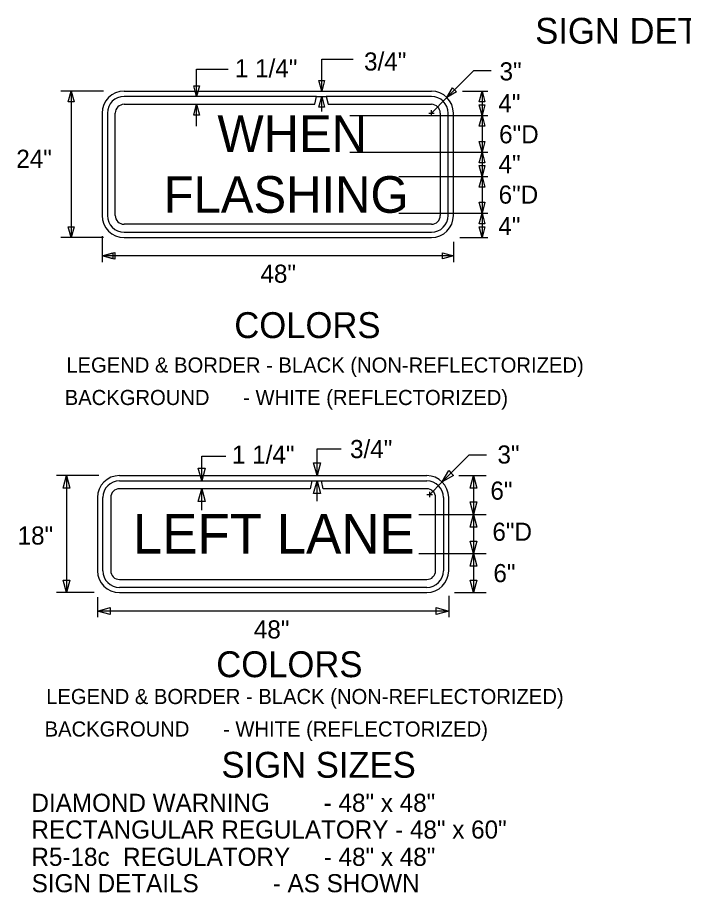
# Model space of a CAD drawing. Extents: x 15278 to 18126, y 1908 to 6555.
# Drawn here: x 17436.4 to 17744.9, y 2193.3 to 2599 of the extents above; entities that cross this region are included whole.
import ezdxf

# ---------------------------------------------------------------- set-up
doc = ezdxf.new("R2010")
doc.units = 0
for name, color, linetype in [('MT_SCRATCH_LEVEL_A', 7, 'Continuous'), ('TYPICAL_EX', 7, 'Continuous'), ('TYPICAL_TEXT_DIMEN_EX', 7, 'Continuous'), ('TYPICAL_TEXT_DIMEN_PR', 7, 'Continuous')]:
    doc.layers.add(name, color=color, linetype=linetype)

msp = doc.modelspace()

# ---------------------------------------------------------------- linework, layer by layer
at = {"layer": 'MT_SCRATCH_LEVEL_A'}
for p, q in [((17577.3, 2579.66), (17591.85, 2579.66)), ((17519.35, 2575.12), (17533.9, 2575.12)), ((17635.31, 2561.91), (17647.66, 2574.32)), ((17655.86, 2574.32), (17647.66, 2574.32)), ((17628.16, 2554.73), (17635.31, 2561.91)), ((17628.16, 2553.51), (17628.16, 2556.01)), ((17626.91, 2554.73), (17629.41, 2554.73)), ((17475.57, 2497.7), (17475.57, 2485.62)), ((17638.33, 2494.97), (17638.33, 2485.62)), ((17638.33, 2488.53), (17475.57, 2488.53)), ((17575.14, 2399.05), (17586.28, 2399.05)), ((17521.69, 2395.58), (17532.82, 2395.58)), ((17633.15, 2383.67), (17645.48, 2396.05)), ((17653.65, 2396.05), (17645.48, 2396.05)), ((17627.35, 2377.85), (17633.15, 2383.67)), ((17626.06, 2377.85), (17628.6, 2377.85)), ((17627.35, 2376.63), (17627.35, 2379.11)), ((17473.44, 2330.34), (17473.44, 2320.93)), ((17636.16, 2330.92), (17636.16, 2320.93)), ((17636.16, 2323.85), (17473.44, 2323.85))]:
    msp.add_line(p, q, dxfattribs=at)
at = {"layer": 'TYPICAL_EX'}
for p, q in [((17485.74, 2564.87), (17628.16, 2564.87)), ((17574.89, 2562.43), (17485.74, 2562.43)), ((17574.07, 2558.77), (17574.89, 2562.43)), ((17574.89, 2562.43), (17579.3, 2562.43)), ((17628.16, 2562.43), (17579.3, 2562.43)), ((17579.3, 2562.43), (17580.24, 2558.77)), ((17485.74, 2558.77), (17574.07, 2558.77)), ((17580.24, 2558.77), (17628.16, 2558.77)), ((17475.57, 2554.7), (17475.57, 2507.22)), ((17478.01, 2554.7), (17478.01, 2507.22)), ((17481.67, 2507.22), (17481.67, 2554.7)), ((17632.23, 2554.7), (17632.23, 2507.22)), ((17635.89, 2507.22), (17635.89, 2554.7)), ((17638.33, 2507.22), (17638.33, 2554.7)), ((17628.16, 2503.15), (17485.74, 2503.15)), ((17485.74, 2499.49), (17628.16, 2499.49)), ((17485.74, 2497.04), (17628.16, 2497.04)), ((17483.61, 2386.63), (17625.99, 2386.63)), ((17483.61, 2384.19), (17572.73, 2384.19)), ((17572.73, 2384.19), (17571.92, 2380.53)), ((17572.73, 2384.19), (17577.14, 2384.19)), ((17571.92, 2380.53), (17483.61, 2380.53)), ((17473.44, 2376.46), (17473.44, 2342.53)), ((17475.88, 2342.53), (17475.88, 2376.46)), ((17479.54, 2376.46), (17479.54, 2342.53)), ((17636.16, 2342.53), (17636.16, 2376.46)), ((17483.61, 2338.46), (17625.99, 2338.46)), ((17625.99, 2334.8), (17483.61, 2334.8)), ((17483.61, 2332.36), (17625.99, 2332.36))]:
    msp.add_line(p, q, dxfattribs=at)
for centre, radius, start, end in [((17485.74, 2554.7), 10.17, 90, 180), ((17628.16, 2554.7), 10.17, 0, 90), ((17485.74, 2554.7), 7.73, 90, 180), ((17628.16, 2554.7), 7.73, 0, 90), ((17485.74, 2554.7), 4.07, 90, 180), ((17628.16, 2554.7), 4.07, 0, 90), ((17485.74, 2507.21), 10.17, 180, 270), ((17485.74, 2507.21), 7.73, 180, 270), ((17485.74, 2507.21), 4.07, 180, 270), ((17628.16, 2507.21), 10.17, 270, 0), ((17628.16, 2507.21), 4.07, 270, 0), ((17628.16, 2507.21), 7.73, 270, 0), ((17483.61, 2376.46), 10.17, 90, 180), ((17625.99, 2376.46), 10.17, 0, 90), ((17483.61, 2376.46), 7.73, 90, 180), ((17483.61, 2376.46), 4.07, 90, 180), ((17483.61, 2342.53), 10.17, 180, 270), ((17483.61, 2342.53), 7.73, 180, 270), ((17483.61, 2342.53), 4.07, 180, 270), ((17625.99, 2342.53), 10.17, 270, 0), ((17625.99, 2342.53), 7.73, 270, 0), ((17625.99, 2342.53), 4.07, 270, 0)]:
    msp.add_arc(centre, radius, start, end, dxfattribs=at)
at = {"layer": 'TYPICAL_TEXT_DIMEN_PR'}
for p, q in [((17577.3, 2564.87), (17577.3, 2579.66)), ((17519.35, 2562.43), (17519.35, 2575.12)), ((17577.3, 2564.87), (17575.96, 2569.85)), ((17575.96, 2569.85), (17577.3, 2569.85)), ((17577.3, 2569.85), (17578.63, 2569.85)), ((17578.63, 2569.85), (17577.3, 2564.87)), ((17476.23, 2564.87), (17456.48, 2564.87)), ((17459.87, 2559.89), (17461.2, 2564.87)), ((17461.2, 2564.87), (17461.2, 2497.04)), ((17461.2, 2564.87), (17462.54, 2559.89)), ((17519.35, 2562.43), (17518.02, 2567.41)), ((17518.02, 2567.41), (17519.35, 2567.41)), ((17519.35, 2567.41), (17520.69, 2567.41)), ((17520.69, 2567.41), (17519.35, 2562.43)), ((17635.31, 2561.91), (17637.88, 2566.39)), ((17639.77, 2564.5), (17635.31, 2561.91)), ((17637.88, 2566.39), (17638.82, 2565.45)), ((17638.82, 2565.45), (17639.77, 2564.5)), ((17642.6, 2564.87), (17654.29, 2564.87)), ((17650.26, 2559.89), (17651.59, 2564.87)), ((17651.59, 2564.87), (17651.59, 2553.55)), ((17651.59, 2564.87), (17652.92, 2559.89)), ((17461.2, 2559.89), (17459.87, 2559.89)), ((17462.54, 2559.89), (17461.2, 2559.89)), ((17575.96, 2557.45), (17577.3, 2562.43)), ((17577.3, 2555.4), (17577.3, 2562.43)), ((17577.3, 2562.43), (17578.63, 2557.45)), ((17651.59, 2559.89), (17650.26, 2559.89)), ((17652.92, 2559.89), (17651.59, 2559.89)), ((17518.02, 2553.78), (17519.35, 2558.77)), ((17519.35, 2548.68), (17519.35, 2558.77)), ((17519.35, 2558.77), (17520.69, 2553.78)), ((17577.3, 2557.45), (17575.96, 2557.45)), ((17578.63, 2557.45), (17577.3, 2557.45)), ((17651.59, 2553.55), (17650.26, 2558.53)), ((17650.26, 2558.53), (17651.59, 2558.53)), ((17651.59, 2558.53), (17652.92, 2558.53)), ((17652.92, 2558.53), (17651.59, 2553.55)), ((17519.35, 2553.78), (17518.02, 2553.78)), ((17520.69, 2553.78), (17519.35, 2553.78)), ((17590.39, 2553.55), (17654.29, 2553.55)), ((17650.26, 2548.57), (17651.59, 2553.55)), ((17651.59, 2553.55), (17651.59, 2536.57)), ((17651.59, 2553.55), (17652.92, 2548.57)), ((17651.59, 2548.57), (17650.26, 2548.57)), ((17652.92, 2548.57), (17651.59, 2548.57)), ((17651.59, 2536.57), (17650.26, 2541.55)), ((17650.26, 2541.55), (17651.59, 2541.55)), ((17651.59, 2541.55), (17652.92, 2541.55)), ((17652.92, 2541.55), (17651.59, 2536.57)), ((17590.39, 2536.57), (17654.29, 2536.57)), ((17650.26, 2531.59), (17651.59, 2536.57)), ((17651.59, 2536.57), (17651.59, 2525.34)), ((17651.59, 2536.57), (17652.92, 2531.59)), ((17651.59, 2531.59), (17650.26, 2531.59)), ((17652.92, 2531.59), (17651.59, 2531.59)), ((17651.59, 2525.34), (17650.26, 2530.33)), ((17650.26, 2530.33), (17651.59, 2530.33)), ((17651.59, 2525.34), (17650.26, 2530.33)), ((17650.26, 2530.33), (17651.59, 2530.33)), ((17651.59, 2530.33), (17652.92, 2530.33)), ((17652.92, 2530.33), (17651.59, 2525.34)), ((17651.59, 2530.33), (17652.92, 2530.33)), ((17652.92, 2530.33), (17651.59, 2525.34)), ((17612.99, 2525.34), (17654.29, 2525.34)), ((17650.26, 2520.36), (17651.59, 2525.34)), ((17651.59, 2525.34), (17651.59, 2508.36)), ((17651.59, 2525.34), (17652.92, 2520.36)), ((17651.59, 2520.36), (17650.26, 2520.36)), ((17652.92, 2520.36), (17651.59, 2520.36)), ((17651.59, 2508.36), (17650.26, 2513.35)), ((17650.26, 2513.35), (17651.59, 2513.35)), ((17651.59, 2508.36), (17650.26, 2513.35)), ((17650.26, 2513.35), (17651.59, 2513.35)), ((17651.59, 2513.35), (17652.92, 2513.35)), ((17652.92, 2513.35), (17651.59, 2508.36)), ((17651.59, 2513.35), (17652.92, 2513.35)), ((17652.92, 2513.35), (17651.59, 2508.36)), ((17612.99, 2508.36), (17654.29, 2508.36)), ((17650.26, 2503.38), (17651.59, 2508.36)), ((17651.59, 2508.36), (17651.59, 2497.04)), ((17651.59, 2508.36), (17652.92, 2503.38)), ((17651.59, 2503.38), (17650.26, 2503.38)), ((17652.92, 2503.38), (17651.59, 2503.38)), ((17461.2, 2497.04), (17459.87, 2502.03)), ((17459.87, 2502.03), (17461.2, 2502.03)), ((17461.2, 2502.03), (17462.54, 2502.03)), ((17462.54, 2502.03), (17461.2, 2497.04)), ((17651.59, 2497.04), (17650.26, 2502.03)), ((17650.26, 2502.03), (17651.59, 2502.03)), ((17651.59, 2502.03), (17652.92, 2502.03)), ((17652.92, 2502.03), (17651.59, 2497.04)), ((17476.23, 2497.04), (17456.48, 2497.04)), ((17641.35, 2497.04), (17654.29, 2497.04)), ((17475.57, 2488.53), (17481.43, 2490.1)), ((17475.57, 2488.53), (17480.55, 2489.87)), ((17481.43, 2486.96), (17475.57, 2488.53)), ((17480.55, 2487.2), (17475.57, 2488.53)), ((17480.55, 2489.87), (17480.55, 2488.53)), ((17480.55, 2488.53), (17480.55, 2487.2)), ((17481.43, 2490.1), (17481.43, 2488.53)), ((17481.43, 2488.53), (17481.43, 2486.96)), ((17633.35, 2488.53), (17633.35, 2489.87)), ((17633.35, 2489.87), (17638.33, 2488.53)), ((17638.33, 2488.53), (17633.35, 2487.2)), ((17633.35, 2487.2), (17633.35, 2488.53)), ((17575.14, 2386.63), (17575.14, 2399.05)), ((17521.69, 2384.19), (17521.69, 2395.58)), ((17521.69, 2384.19), (17520.12, 2390.05)), ((17520.12, 2390.05), (17521.69, 2390.05)), ((17521.69, 2390.05), (17523.26, 2390.05)), ((17523.26, 2390.05), (17521.69, 2384.19)), ((17575.14, 2386.63), (17573.57, 2392.49)), ((17573.57, 2392.49), (17575.14, 2392.49)), ((17575.14, 2392.49), (17576.71, 2392.49)), ((17576.71, 2392.49), (17575.14, 2386.63)), ((17474.08, 2386.63), (17454.36, 2386.63)), ((17457.5, 2380.77), (17459.07, 2386.63)), ((17459.07, 2386.63), (17459.07, 2332.36)), ((17459.07, 2386.63), (17460.64, 2380.77)), ((17633.15, 2383.67), (17636.17, 2388.93)), ((17638.4, 2386.72), (17633.15, 2383.67)), ((17636.17, 2388.93), (17637.28, 2387.83)), ((17637.28, 2387.83), (17638.4, 2386.72)), ((17640.78, 2386.63), (17653.49, 2386.63)), ((17646.12, 2380.77), (17647.69, 2386.63)), ((17647.69, 2386.63), (17647.69, 2368.54)), ((17647.69, 2386.63), (17649.26, 2380.77)), ((17483.61, 2384.19), (17572.73, 2384.19)), ((17572.73, 2384.19), (17571.92, 2380.53)), ((17573.57, 2378.33), (17575.14, 2384.19)), ((17575.14, 2374.83), (17575.14, 2384.19)), ((17575.14, 2384.19), (17576.71, 2378.33)), ((17578.06, 2380.53), (17577.14, 2384.19)), ((17577.14, 2384.19), (17625.99, 2384.19)), ((17459.07, 2380.77), (17457.5, 2380.77)), ((17460.64, 2380.77), (17459.07, 2380.77)), ((17571.92, 2380.53), (17483.61, 2380.53)), ((17520.12, 2374.67), (17521.69, 2380.53)), ((17521.69, 2370.54), (17521.69, 2380.53)), ((17521.69, 2380.53), (17523.26, 2374.67)), ((17575.14, 2378.33), (17573.57, 2378.33)), ((17576.71, 2378.33), (17575.14, 2378.33)), ((17625.99, 2380.53), (17578.06, 2380.53)), ((17647.69, 2380.77), (17646.12, 2380.77)), ((17649.26, 2380.77), (17647.69, 2380.77)), ((17475.88, 2342.53), (17475.88, 2376.46)), ((17479.54, 2376.46), (17479.54, 2342.53)), ((17521.69, 2374.67), (17520.12, 2374.67)), ((17523.26, 2374.67), (17521.69, 2374.67)), ((17630.06, 2342.53), (17630.06, 2376.46)), ((17633.72, 2376.46), (17633.72, 2342.53)), ((17647.69, 2368.54), (17646.12, 2374.4)), ((17646.12, 2374.4), (17647.69, 2374.4)), ((17647.69, 2374.4), (17649.26, 2374.4)), ((17649.26, 2374.4), (17647.69, 2368.54)), ((17622.35, 2368.54), (17653.49, 2368.54)), ((17646.12, 2362.68), (17647.69, 2368.54)), ((17647.69, 2368.54), (17647.69, 2350.45)), ((17647.69, 2368.54), (17649.26, 2362.68)), ((17647.69, 2362.68), (17646.12, 2362.68)), ((17649.26, 2362.68), (17647.69, 2362.68)), ((17647.69, 2350.45), (17646.12, 2356.31)), ((17646.12, 2356.31), (17647.69, 2356.31)), ((17647.69, 2356.31), (17649.26, 2356.31)), ((17649.26, 2356.31), (17647.69, 2350.45)), ((17622.35, 2350.45), (17653.49, 2350.45)), ((17646.12, 2344.59), (17647.69, 2350.45)), ((17647.69, 2350.45), (17647.69, 2332.36)), ((17647.69, 2350.45), (17649.26, 2344.59)), ((17647.69, 2344.59), (17646.12, 2344.59)), ((17649.26, 2344.59), (17647.69, 2344.59)), ((17459.07, 2332.36), (17457.5, 2338.22)), ((17457.5, 2338.22), (17459.07, 2338.22)), ((17459.07, 2338.22), (17460.64, 2338.22)), ((17460.64, 2338.22), (17459.07, 2332.36)), ((17483.61, 2338.46), (17625.99, 2338.46)), ((17647.69, 2332.36), (17646.12, 2338.22)), ((17646.12, 2338.22), (17647.69, 2338.22)), ((17647.69, 2338.22), (17649.26, 2338.22)), ((17649.26, 2338.22), (17647.69, 2332.36)), ((17625.99, 2334.8), (17483.61, 2334.8)), ((17471.81, 2332.36), (17454.36, 2332.36)), ((17638.78, 2332.36), (17653.49, 2332.36)), ((17473.44, 2323.85), (17479.3, 2325.42)), ((17479.3, 2325.42), (17479.3, 2323.85)), ((17630.3, 2323.85), (17630.3, 2325.42)), ((17630.3, 2325.42), (17636.16, 2323.85)), ((17479.3, 2322.28), (17473.44, 2323.85)), ((17479.3, 2323.85), (17479.3, 2322.28)), ((17636.16, 2323.85), (17630.3, 2322.28)), ((17630.3, 2322.28), (17630.3, 2323.85))]:
    msp.add_line(p, q, dxfattribs=at)
for centre, radius, start, end in [((17483.61, 2376.46), 7.73, 90, 180), ((17625.99, 2376.46), 7.73, 0, 90), ((17483.61, 2376.46), 4.07, 90, 180), ((17625.99, 2376.46), 4.07, 0, 90), ((17483.61, 2342.53), 7.73, 180, 270), ((17483.61, 2342.53), 4.07, 180, 270), ((17625.99, 2342.53), 4.07, 270, 0), ((17625.99, 2342.53), 7.73, 270, 0)]:
    msp.add_arc(centre, radius, start, end, dxfattribs=at)

# ---------------------------------------------------------------- texts
at = {"layer": 'TYPICAL_TEXT_DIMEN_EX'}
for s, height, p in [('WHEN   ', 16.968, (17528.99, 2536.66)), ('FLASHING', 16.968, (17504.08, 2508.48)), ('LEFT LANE', 18.308, (17489.8, 2350.51))]:
    msp.add_text(s, height=height, dxfattribs=at).set_placement(p)
at = {"layer": 'TYPICAL_TEXT_DIMEN_PR'}
for s, height, p in [('SIGN DETAILS', 12, (17676.24, 2586.85)), ('1 1/4"', 8.4, (17537.08, 2571.3)), ('3/4"', 8.4, (17596.93, 2574.44)), ('3"', 8.4, (17659.72, 2569.85)), ('4"', 8.4, (17659.16, 2555.08)), ('6"D', 8.4, (17659.51, 2540.69)), ('24"', 8.4, (17435.79, 2529.32)), ('4"', 8.4, (17659.25, 2526.82)), ('6"D', 8.4, (17659.28, 2512.72)), ('4"', 8.4, (17659.16, 2498.19)), ('48"', 8.4, (17548.92, 2476.04)), ('COLORS', 12, (17536.8, 2450.4)), ('LEGEND & BORDER - BLACK (NON-REFLECTORIZED)', 7, (17458.96, 2434.4)), ('BACKGROUND      - WHITE (REFLECTORIZED)', 7, (17458.23, 2419.35)), ('3/4"', 8.4, (17590.44, 2394.74)), ('1 1/4"', 8.4, (17535.73, 2392.16)), ('3"', 8.4, (17658.75, 2392.22)), ('6"', 8.4, (17655.48, 2375.47)), ('18"', 8.4, (17436.4, 2354.65)), ('6"D', 8.4, (17656.41, 2356.41)), ('6"', 8.4, (17656.87, 2337.23)), ('48"', 8.4, (17545.87, 2311.12)), ('COLORS', 12, (17528.44, 2293.17)), ('LEGEND & BORDER - BLACK (NON-REFLECTORIZED)', 7, (17449.64, 2280.71)), ('BACKGROUND      - WHITE (REFLECTORIZED)', 7, (17448.91, 2265.66)), ('SIGN SIZES', 12, (17530.86, 2246.56)), ('DIAMOND WARNING        - 48" x 48"', 8.4, (17442.82, 2230.74)), ('RECTANGULAR REGULATORY - 48" x 60"', 8.4, (17442.82, 2218.34)), ('R5-18c  REGULATORY     - 48" x 48"', 8.4, (17442.82, 2205.69)), ('SIGN DETAILS           - AS SHOWN', 8.4, (17442.9, 2193.46))]:
    msp.add_text(s, height=height, dxfattribs=at).set_placement(p)

doc.saveas('drawing.dxf')
